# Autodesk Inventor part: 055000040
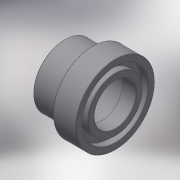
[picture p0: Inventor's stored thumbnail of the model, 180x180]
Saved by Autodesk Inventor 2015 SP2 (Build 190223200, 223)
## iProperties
Created: 2017-10
Part Number: 055000040
Material: Generic
Description: PLASSON FLANGE AD.+O-RING-CE 40
Document SubType Name: Modeling
Designer: KIM
Density: 1 g/cm^3
Appearance: Default
Author: KIM
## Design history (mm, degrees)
derived "055000.ipt"
feature "Solid1::055000.ipt"
tag "TaggingFeature1"
body "Solid1"
other parameters: "d0" = 34, "d3" = 36, "d4" = 13, "d5" = 26, "d6" = 61, "d8" = 3.9, "d11" = 0.4, "d12" = 3.9, "d15" = 3.75, "E_1" = 61, "l_" = 26, "B_" = 13, "H_" = 34, "d14" = 12.5
